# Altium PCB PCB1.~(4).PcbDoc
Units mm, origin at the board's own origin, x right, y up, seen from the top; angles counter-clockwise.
Board outline 127 x 101.6 mm, 3 copper layers (Top Layer, Internal Plane 1, Bottom Layer); 15 components, 13 nets, 51 pads, 0 vias.
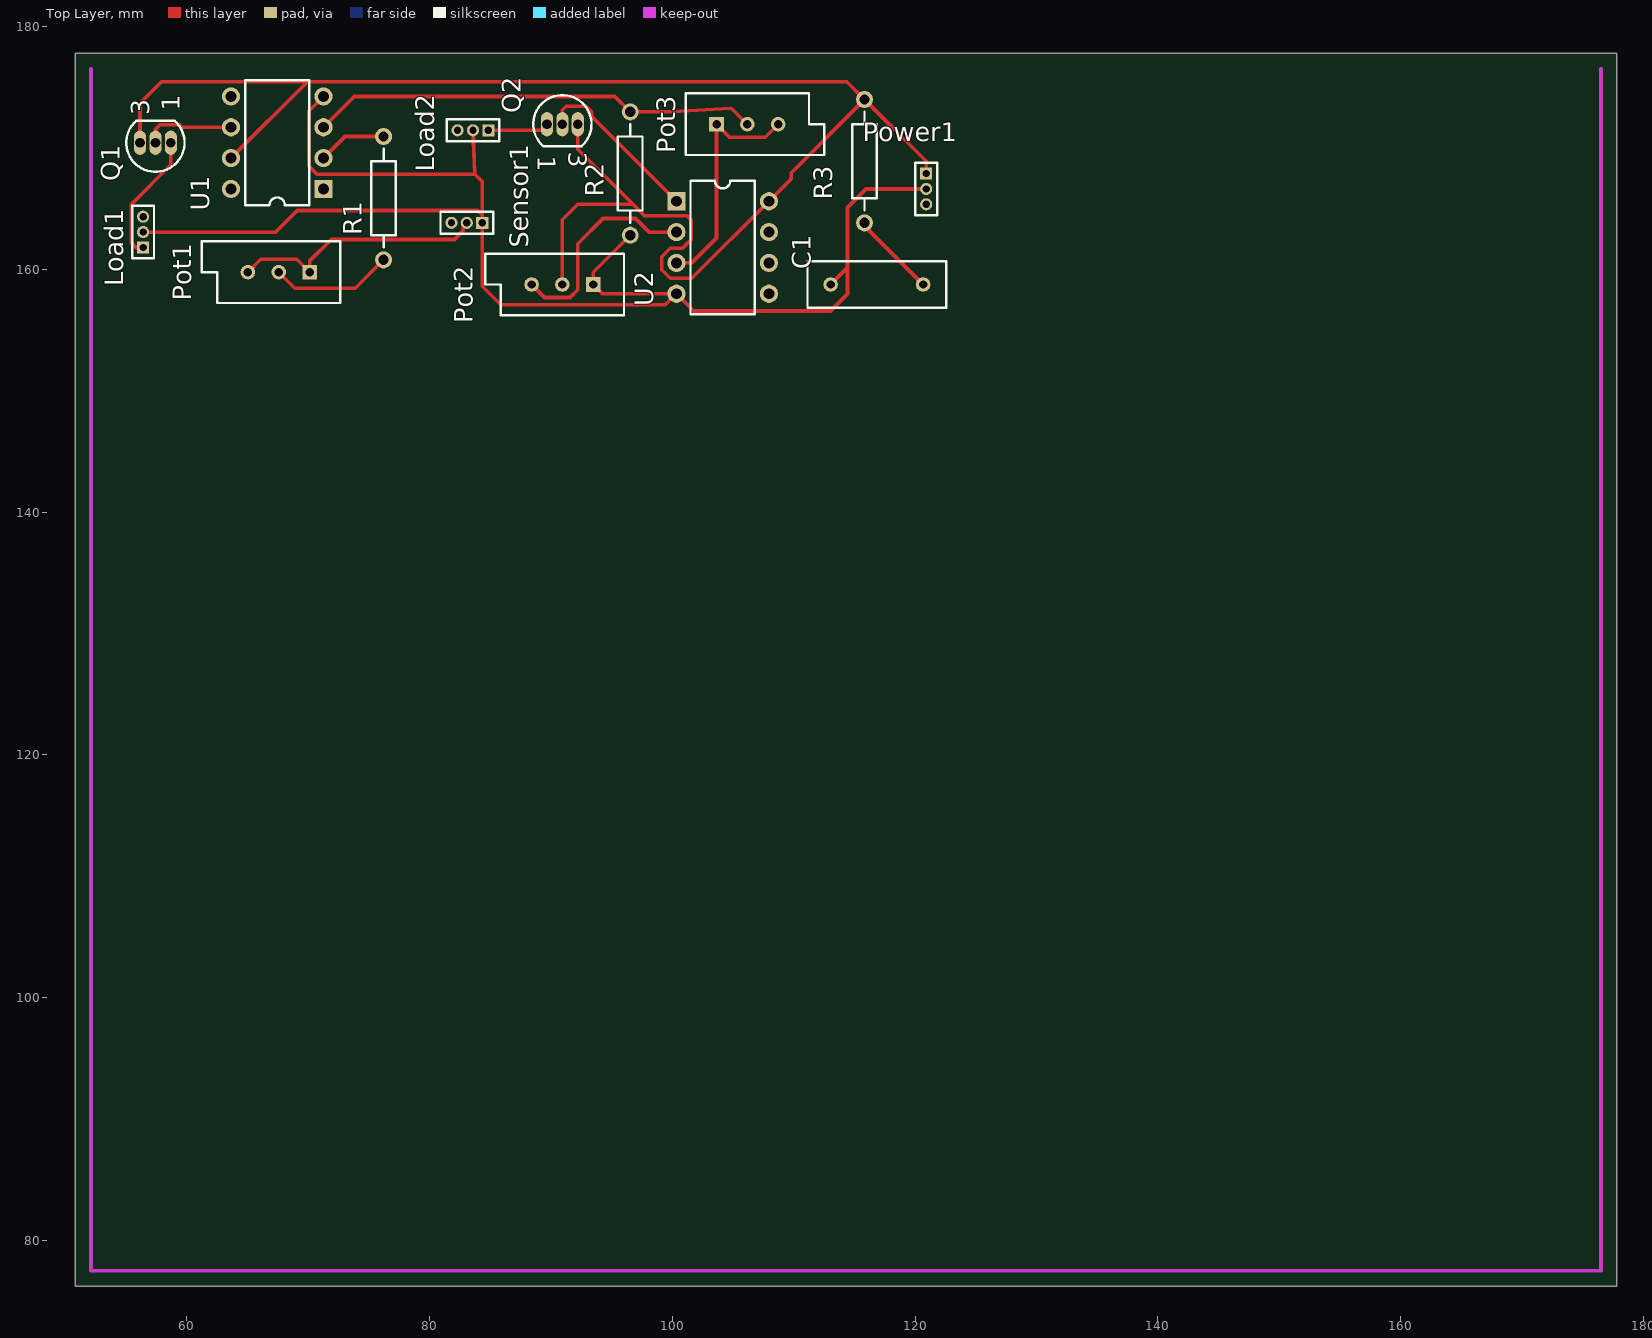
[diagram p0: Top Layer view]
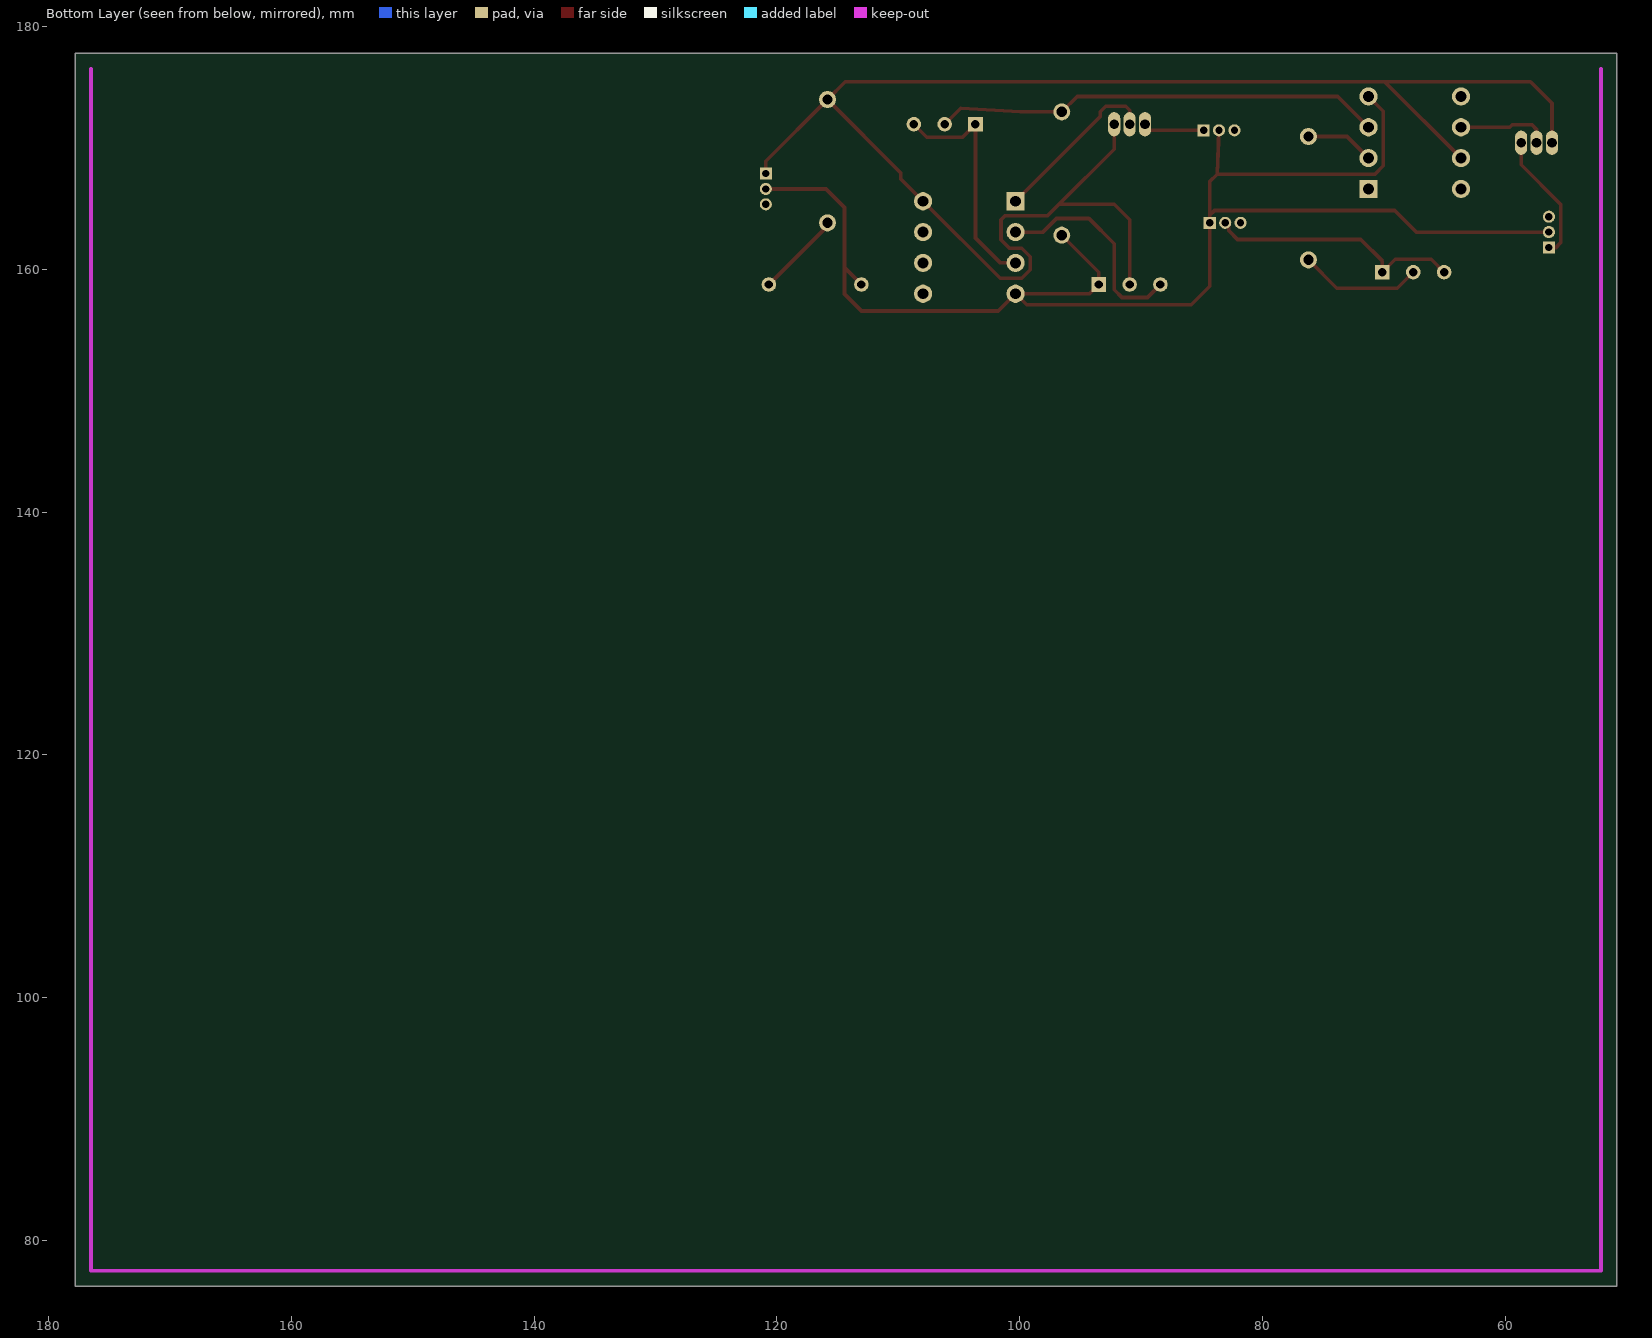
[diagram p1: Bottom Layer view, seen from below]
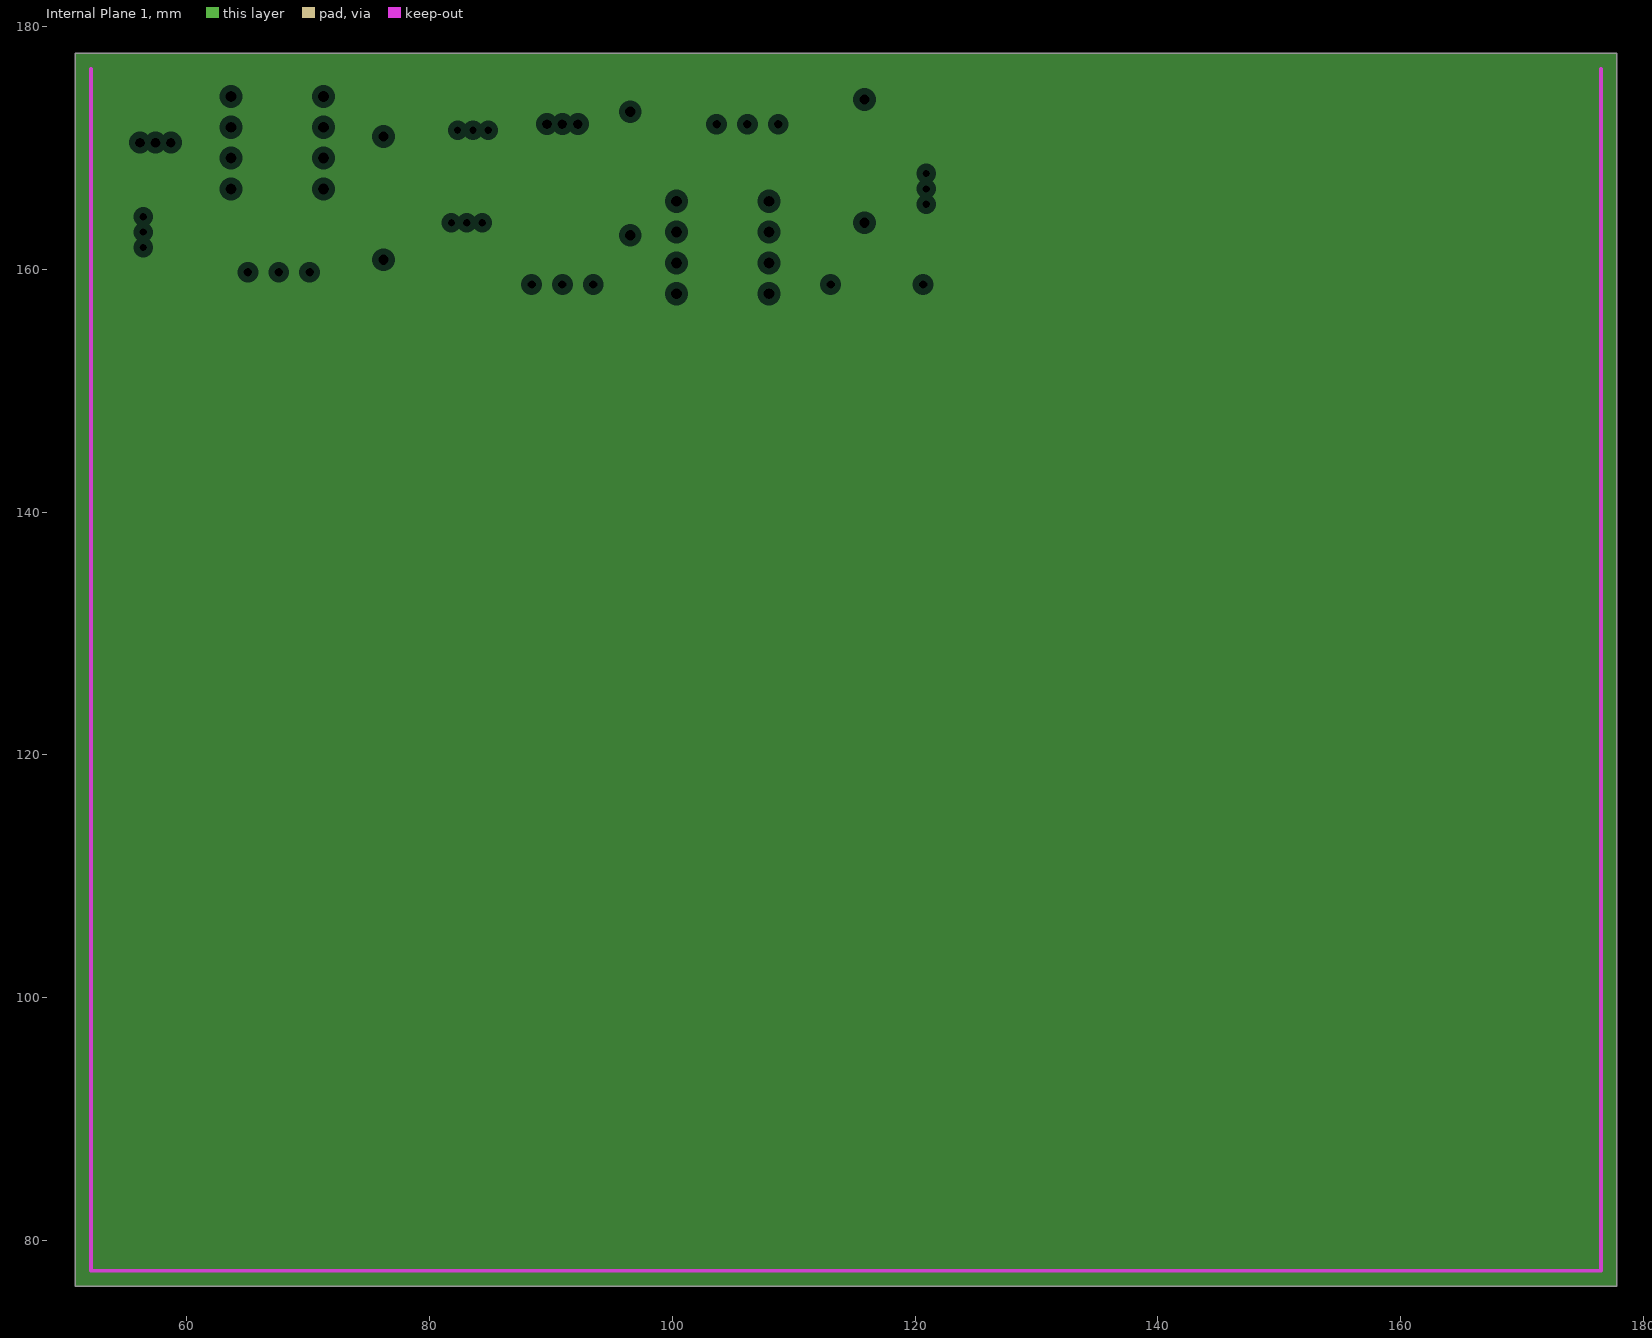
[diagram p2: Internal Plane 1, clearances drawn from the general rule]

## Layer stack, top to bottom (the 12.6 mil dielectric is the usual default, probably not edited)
Top Layer: signal copper 0.0356
Dielectric: dielectric 0.32, FR-4, Dk 4.8
Internal Plane 1: plane copper 0.0356
Dielectric: dielectric 0.32, FR-4, Dk 4.8
Bottom Layer: signal copper 0.0356

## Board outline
50.8,76.2 177.8,76.2 177.8,177.8 50.8,177.8

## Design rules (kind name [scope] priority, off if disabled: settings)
Clearance [All] p1: gap=0.3
ComponentClearance [All] p1: gap=0.254 collisioncheckmode=3 verticalgap=0.254
PlaneClearance [All] p1: clearance=0.508
PlaneConnect [All] p1: planeconnectstyle=Relief reliefexpansion=0.508 reliefentries=4 reliefconductorwidth=0.254 reliefairgap=0.254
PolygonConnect [All] p1: connectstyle=Relief reliefconductorwidth=0.254 reliefentries=4 polygonreliefangle="90 Angle"
RoomDefinition Sheet1 [InComponentClass('Sheet1')] p1: confinementstyle=ConfineIn formatcopy=TRUE lockcomponents=FALSE outline 0,0 50.8,0 50.8,25.4 0,25.4
RoutingVias [All] p1: holewidth=0.8 width=1.6 viastyle="Through Hole" minholewidth=0.711 minwidth=1.27 maxholewidth=0.711 maxwidth=1.27
SolderMaskExpansion [All] p1: expansion=0.102
TestPointUsage [All] p1: valid=0 allowmultiple=FALSE
Testpoint [All] p1: side=15 testpointundercomponent=TRUE minsize=1.016 maxsize=2.54 preferedsize=1.524 minholesize=0 maxholesize=1.016 preferedholesize=0.813 testpointgrid=0.025 style=1023 order=0-112345678
Width [All] p1: maxlimit=0.3 minlimit=0.3 preferedwidth=0.3
16 further rules are at their usual default settings.

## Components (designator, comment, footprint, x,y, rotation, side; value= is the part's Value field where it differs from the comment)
C1 "Cap" RAD-0.3 116.84,158.75 r0 top
Load1 "MHDR1X3" MHDR1X3 56.388,161.798 r90 top
Load2 "MHDR1X3" MHDR1X3 84.836,171.45 r180 top
Pot1 "RPot" VR5 67.564,159.766 r180 top
Pot2 "RPot" VR5 90.932,158.75 r180 top (schematic designator Pot3)
Pot3 "RPot" VR5 106.172,171.958 r0 top (schematic designator Pot2)
Power1 "MHDR1X3" MHDR1X3 120.904,167.894 r270 top (schematic designator Power)
Q1 "BC547A" SOT54 57.404,170.434 r90 top
Q2 "BC547A" SOT54 90.932,171.958 r270 top
R1 "Res2" AXIAL-0.4 76.2,165.862 r90 top
R2 "Res2" AXIAL-0.4 96.52,167.894 r90 top
R3 "Res2" AXIAL-0.4 115.824,168.91 r90 top
Sensor1 "MHDR1X3" MHDR1X3 84.328,163.83 r180 top (schematic designator Sensor)
U1 "LM741J/883" N08E 67.437,170.434 r90 top
U2 "LM393P" P008 104.14,161.798 r270 top

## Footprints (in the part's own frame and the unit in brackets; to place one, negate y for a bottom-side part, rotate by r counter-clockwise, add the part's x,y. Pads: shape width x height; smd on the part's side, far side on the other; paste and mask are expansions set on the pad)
AXIAL-0.4 [mm] "Resistor; 2 Leads"
  round 1.4 hole 0.85: 1(-5.08,0) 2(5.08,0)
  silkscreen extent -4.06,-1.02 4.06,1.02
MHDR1X3 [mm] "Connector; Header; 3 Position"
  rect 1x1 hole 0.6: 1(0,0)
  round 1 hole 0.6: 2(1.27,0) 3(2.54,0)
  silkscreen extent -0.9,-0.9 3.44,0.9
N08E [mm] "DIP; 8 Leads; Row Spacing 7.62 mm; Pitch 2.54 mm"
  rect 1.5x1.5 hole 0.9: 1(-3.81,-3.81)
  round 1.5 hole 0.9: 2(-1.27,-3.81) 3(1.27,-3.81) 4(3.81,-3.81) 5(3.81,3.81) 6(1.27,3.81) 7(-1.27,3.81) 8(-3.81,3.81)
  silkscreen extent -5.15,-2.65 5.15,2.65
P008 [mm] "DIP; 8 Leads; Row Spacing 7.62 mm; Pitch 2.54 mm"
  rect 1.5x1.5 hole 0.9: 1(-3.81,-3.81)
  round 1.5 hole 0.9: 2(-1.27,-3.81) 3(1.27,-3.81) 4(3.81,-3.81) 5(3.81,3.81) 6(1.27,3.81) 7(-1.27,3.81) 8(-3.81,3.81)
  silkscreen extent -5.5,-2.65 5.5,2.65
RAD-0.3 [mm] "Capacitor; 2 Leads"
  round 1.2 hole 0.7: 1(-3.81,0) 2(3.81,0)
  silkscreen extent -5.71,-1.91 5.71,1.91
SOT54 [mm] "TO, Flat Index; 3 In-Line, Axial Leads; Body Dia. 4.6mm; Leads 0.48 x 0.45 mm (max)"
  oval 2x1 hole 0.8: 1(0,-1.27) 2(0,0) 3(0,1.27)
  silkscreen extent -2.4,-2.4 1.8,2.4
VR5 [mm] "Potentiometer; 3 Leads"
  rect 1.2x1.2 hole 0.7: 1(-2.54,0)
  round 1.2 hole 0.7: 2(0,0) 3(2.54,0)
  silkscreen extent -5.08,-2.54 6.35,2.54

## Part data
C1: "Capacitor"
Load1 Load2 Power1 Sensor1: "Header, 3-Pin"
Pot1 Pot2 Pot3: "Potentiometer"
Q1 Q2: "NPN General-purpose Transistor"
R1 R2 R3: "Resistor"
U1: "Operational Amplifier"
U2: "Dual Differential Comparator"

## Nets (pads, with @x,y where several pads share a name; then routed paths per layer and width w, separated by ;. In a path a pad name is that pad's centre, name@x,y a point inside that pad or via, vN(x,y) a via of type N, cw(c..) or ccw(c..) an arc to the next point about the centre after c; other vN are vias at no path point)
GND: C1.1 Load1.2 Load2.2 Pot2.1 Power1.2 R2.1 Sensor1.1 U1.4 U2.4 | length 123.1
  Top Layer w0.3: Load1.2 67.31,163.068 69.088,164.846 83.947,164.846 84.328,164.465 ; U1.4 70.028,173.025 70.028,168.529 70.714,167.843 83.718,167.843 ; Load2.2 83.718,167.843 ; R2.1 93.472,159.766 Pot2.1 94.234,157.988 U2.4 ; C1.1 114.427,160.147 ; Power1.2 115.951,166.624 114.427,165.1 114.427,160.147 ; 83.718,167.843 84.328,167.234 84.328,164.465 ; 84.328,164.465 Sensor1.1 84.328,158.598 85.852,157.074 99.416,157.074 U2.4 ; U2.4 101.752,156.566 113.03,156.566 114.427,157.963 114.427,160.147
NetC1_2: C1.2 R3.1 | length 7.1
  Top Layer w0.3: R3.1 115.824,163.576 C1.2
NetLoad1_1: Load1.1 Q1.1 | length 10.7
  Top Layer w0.3: Load1.1 55.804,161.798 55.423,162.179 55.423,165.354 58.674,168.605 Q1.1
NetLoad2_1: Load2.1 Q2.1 | length 5.3
  Top Layer w0.3: Load2.1 89.662,171.45 Q2.1
NetPot1_1: Pot1.1 Pot1.3 Sensor1.2 | length 21.3
  Top Layer w0.3: Pot1.3 66.091,160.833 69.037,160.833 Pot1.1 70.104,160.68 71.882,162.458 82.042,162.458 82.753,163.17 82.753,163.525 Sensor1.2
NetPot1_2: Pot1.2 R1.1 | length 10.2
  Top Layer w0.3: Pot1.2 68.885,158.445 73.863,158.445 R1.1
NetPot2_1: Pot3.1 Pot3.3 U2.3 | length 19.5
  Top Layer w0.3: U2.3 101.576,160.528 103.632,162.584 Pot3.1 104.699,170.891 107.645,170.891 Pot3.3
NetPot2_2: Pot3.2 R2.2 U1.3 | length 37.1
  Top Layer w0.3: U1.3 73.787,174.244 95.25,174.244 R2.2 99.924,172.974 104.851,173.279 Pot3.2
NetPot3_3: Pot2.3 U2.2 | length 17.8
  Top Layer w0.3: Pot2.3 89.459,157.683 91.567,157.683 92.202,158.318 92.202,162.103 94.285,164.186 96.952,164.186 98.07,163.068 U2.2
NetQ1_2: Q1.2 U1.6 | length 7.6
  Top Layer w0.3: Q1.2 57.404,171.526 57.785,171.907 59.411,171.907 59.614,171.704 U1.6
NetQ2_2: Q2.2 U2.1 | length 14.1
  Top Layer w0.3: Q2.2 90.932,173.114 91.249,173.431 92.888,173.431 93.345,172.974 93.345,172.593 U2.1
NetR1_2: R1.2 U1.2 | length 5.7
  Top Layer w0.3: U1.2 73.025,170.942 R1.2
VCC: Pot2.2 Power1.1 Q1.3 Q2.3 R3.2 U1.7 U2.8 | length 136
  Top Layer w0.3: Q1.3 56.134,173.685 57.912,175.463 69.926,175.463 ; U1.7 69.926,175.463 ; Pot2.2 90.932,164.084 92.202,165.354 96.749,165.354 ; Q2.3 92.202,169.901 96.749,165.354 ; Power1.1 120.904,168.91 R3.2 ; 69.926,175.463 114.351,175.463 R3.2 ; 96.749,165.354 97.695,164.408 101.206,164.408 101.53,164.084 101.53,162.439 100.838,161.747 99.822,161.747 99.111,161.036 99.111,159.969 99.822,159.258 101.6,159.258 U2.8 109.779,167.437 109.779,167.945 R3.2
pads on no net: Load1.3 Load2.3 Power1.3 Sensor1.3 U1.1 U1.5 U1.8 U2.5 U2.6 U2.7

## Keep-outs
Keep-Out Layer:
  lines w0.3: 52.1,176.5 52.1,77.5 176.5,77.5 176.5,176.5

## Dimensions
52.1,77.5 to 176.5,77.5 on Mechanical 1
52.1,77.5 to 52.1,176.5 on Mechanical 1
